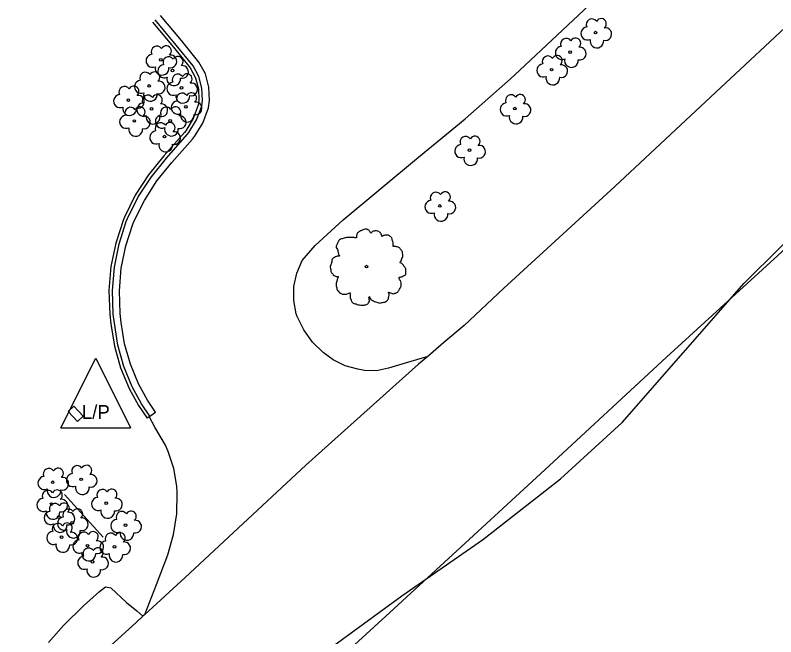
# Model space of a CAD drawing. Extents: x 2161152 to 2175754, y 602179 to 617749.
# Drawn here: x 2162727.5 to 2162836.6, y 605296.7 to 605385.9 of the extents above; entities that cross this region are included whole.
import ezdxf

# ---------------------------------------------------------------- set-up
doc = ezdxf.new("R2010")
doc.units = 0
for name, color, linetype in [('RD_EX_BldgApp_Sign', 7, 'Continuous'), ('RD_EX_Conc_Curb', 7, 'Continuous'), ('RD_EX_Conc_Gutter', 7, 'Continuous'), ('RD_EX_Parking_Asphalt', 7, 'Continuous'), ('RD_EX_Road', 7, 'Continuous'), ('RD_EX_UT', 7, 'Continuous'), ('RD_EX_VEG', 7, 'Continuous')]:
    doc.layers.add(name, color=color, linetype=linetype)

msp = doc.modelspace()

# ---------------------------------------------------------------- linework, layer by layer
at = {"layer": 'RD_EX_BldgApp_Sign'}
msp.add_line((2162734.54, 605317.11), (2162740.12, 605310.98), dxfattribs=at)
at = {"layer": 'RD_EX_Conc_Curb'}
msp.add_lwpolyline([(2162747.19, 605384.92), (2162750.21, 605381.32), (2162752.59, 605378.37), (2162753.36, 605376.93), (2162753.79, 605375.36), (2162753.85, 605373.72), (2162753.76, 605373), (2162753.04, 605371.1), (2162751.97, 605369.34), (2162751.78, 605369.09), (2162748.83, 605365.72), (2162746.62, 605363.02), (2162744.71, 605360.07), (2162743.16, 605356.93), (2162742.96, 605356.46), (2162741.9, 605353.2), (2162741.22, 605349.82), (2162740.94, 605346.39), (2162741.06, 605342.96), (2162741.22, 605341.61), (2162741.72, 605338.41), (2162742.61, 605335.29), (2162743.85, 605332.3), (2162745.2, 605329.87), (2162746.4, 605328.08), (2162746.4, 605328.09), (2162746.69, 605328.28), (2162746.81, 605328.36), (2162745.62, 605330.13), (2162744.29, 605332.55), (2162743.07, 605335.48), (2162742.21, 605338.54), (2162741.72, 605341.68), (2162741.56, 605343), (2162741.44, 605346.38), (2162741.72, 605349.75), (2162742.39, 605353.07), (2162743.43, 605356.29), (2162743.61, 605356.72), (2162745.15, 605359.82), (2162747.02, 605362.72), (2162749.21, 605365.4), (2162752.17, 605368.78), (2162752.38, 605369.06), (2162753.49, 605370.88), (2162754.25, 605372.88), (2162754.35, 605373.7), (2162754.29, 605375.44), (2162753.83, 605377.12), (2162753.01, 605378.65), (2162750.6, 605381.63), (2162747.57, 605385.24)], dxfattribs=at)
at = {"layer": 'RD_EX_Conc_Gutter'}
msp.add_lwpolyline([(2162746.81, 605328.36), (2162747.64, 605328.92), (2162746.48, 605330.66), (2162745.19, 605332.99), (2162744.02, 605335.81), (2162743.19, 605338.75), (2162742.71, 605341.82), (2162742.56, 605343.08), (2162742.45, 605346.36), (2162742.71, 605349.61), (2162743.35, 605352.82), (2162744.37, 605355.94), (2162744.52, 605356.31), (2162746.02, 605359.33), (2162747.83, 605362.13), (2162749.98, 605364.75), (2162752.94, 605368.14), (2162753.21, 605368.5), (2162754.39, 605370.44), (2162755.23, 605372.63), (2162755.36, 605373.65), (2162755.28, 605375.59), (2162754.77, 605377.49), (2162753.85, 605379.2), (2162751.37, 605382.27), (2162748.34, 605385.89)], dxfattribs=at)
at = {"layer": 'RD_EX_Parking_Asphalt'}
for points in [[(2162786.7, 605336.94), (2162783.47, 605335.98), (2162781.08, 605335.25), (2162779.36, 605334.88), (2162777.61, 605334.9), (2162776.68, 605335.08), (2162774.85, 605335.58), (2162773.13, 605336.43), (2162771.7, 605337.51), (2162770.15, 605338.99), (2162768.89, 605340.73), (2162767.97, 605342.67), (2162767.83, 605343.04), (2162767.46, 605344.98), (2162767.47, 605346.96), (2162767.88, 605348.9), (2162768.66, 605350.71), (2162770.55, 605352.84), (2162774.54, 605356.55), (2162785.35, 605365.55), (2162792.07, 605371.03), (2162798.56, 605376.79), (2162799.91, 605378.05), (2162815.23, 605392.44)], [(2162746.09, 605299.88), (2162747.78, 605304.17), (2162749.38, 605308.43), (2162750.22, 605311.34), (2162750.68, 605314.33), (2162750.75, 605317.36), (2162750.69, 605318.32), (2162750.26, 605320.85), (2162749.45, 605323.28), (2162749.04, 605324.19), (2162747.5, 605326.77), (2162746.69, 605328.28)]]:
    msp.add_lwpolyline(points, dxfattribs=at)
at = {"layer": 'RD_EX_Road'}
for points in [[(2162917.02, 605457), (2162901.98, 605443.14), (2162896.04, 605437.72), (2162894.14, 605435.98), (2162878, 605421.14), (2162857.37, 605402.08), (2162850.22, 605395.49), (2162842.2, 605388.11), (2162825.87, 605372.86), (2162813.54, 605361.31), (2162797.56, 605346.66), (2162791.94, 605341.38), (2162789, 605338.93), (2162786.7, 605336.94), (2162785.38, 605335.8), (2162769.2, 605321.32), (2162751.87, 605305.17), (2162746.09, 605299.88), (2162745.82, 605299.64), (2162744.83, 605298.73), (2162729.3, 605284.63)], [(2162610.98, 605142.74), (2162631.96, 605161.97), (2162654.13, 605182.45), (2162675.54, 605202.17), (2162697.6, 605222.63), (2162722.31, 605245.68), (2162738.68, 605260.91), (2162760.98, 605281.6), (2162781.23, 605300.15), (2162803.5, 605320.65), (2162820.96, 605336.83), (2162841.34, 605355.43), (2162863.86, 605376.35), (2162885.23, 605396.1), (2162904.45, 605413.96), (2162926, 605434.03)], [(2162732.26, 605295.86), (2162734.43, 605298.29), (2162737.28, 605301.11), (2162739.56, 605303.19), (2162740.43, 605303.86), (2162741.23, 605303.68), (2162743.47, 605301.6), (2162744.95, 605300.4), (2162745.82, 605299.64)]]:
    msp.add_lwpolyline(points, dxfattribs=at)
at = {"layer": 'RD_EX_UT'}
for p, q in [((2162734.04, 605326.67), (2162739.04, 605336.67)), ((2162739.04, 605336.67), (2162744.04, 605326.67)), ((2162734.04, 605326.67), (2162744.04, 605326.67))]:
    msp.add_line(p, q, dxfattribs=at)
msp.add_lwpolyline([(2162735.07, 605329.03), (2162736.42, 605327.59), (2162737.25, 605328.36), (2162735.9, 605329.81), (2162735.07, 605329.03)], dxfattribs=at)
at = {"layer": 'RD_EX_VEG'}
msp.add_lwpolyline([(2162768.94, 605292.32), (2162782.97, 605302.54), (2162794.55, 605310.58), (2162805.73, 605319.37), (2162814.62, 605327.42), (2162832.11, 605347.44), (2162847.75, 605362.93), (2162864.42, 605376.7), (2162880.18, 605392.38), (2162895.34, 605405.76), (2162910.37, 605417.3)], dxfattribs=at)
for centre, radius in [((2162810.79, 605383.42), 0.188), ((2162807.12, 605380.62), 0.188), ((2162748.37, 605379.5), 0.188), ((2162804.47, 605378.1), 0.188), ((2162750.05, 605377.98), 0.188), ((2162746.71, 605375.76), 0.188), ((2162751.36, 605375.48), 0.188), ((2162743.72, 605373.71), 0.188), ((2162751.99, 605372.76), 0.188), ((2162747.06, 605372.48), 0.188), ((2162799.2, 605372.51), 0.188), ((2162744.58, 605370.73), 0.188), ((2162749.71, 605370.76), 0.188), ((2162748.91, 605368.49), 0.188), ((2162792.68, 605366.53), 0.188), ((2162788.41, 605358.53), 0.188), ((2162777.91, 605349.82), 0.188), ((2162777.9, 605349.81), 0.000075), ((2162736.94, 605319.28), 0.188), ((2162732.86, 605318.86), 0.188), ((2162740.55, 605315.87), 0.188), ((2162732.71, 605315.73), 0.188), ((2162733.74, 605313.85), 0.188), ((2162735.66, 605313.03), 0.188), ((2162743.32, 605312.7), 0.188), ((2162734.14, 605310.99), 0.188), ((2162737.87, 605309.75), 0.188), ((2162741.74, 605309.59), 0.188), ((2162738.57, 605307.43), 0.188)]:
    msp.add_circle(centre, radius, dxfattribs=at)
for centre, radius, start, end in [((2162810.25, 605384.58), 0.813, 34.9763, 204.756), ((2162811.57, 605384.69), 0.746, 308.7626, 152.0467), ((2162809.62, 605383.3), 0.943, 96.4518, 294.734), ((2162812.17, 605383.21), 0.914, 256.5667, 98.1046), ((2162806.58, 605381.78), 0.813, 34.9763, 204.756), ((2162807.91, 605381.9), 0.746, 308.7626, 152.0467), ((2162810.97, 605382.22), 0.988, 166.8827, 5.7589), ((2162747.83, 605380.66), 0.813, 34.9763, 204.756), ((2162749.16, 605380.77), 0.746, 308.7626, 152.0467), ((2162805.95, 605380.5), 0.943, 96.4518, 294.734), ((2162808.5, 605380.41), 0.914, 256.5667, 98.1046), ((2162747.2, 605379.38), 0.943, 96.4518, 294.734), ((2162749.51, 605379.14), 0.813, 34.9763, 204.756), ((2162749.75, 605379.29), 0.914, 256.5667, 98.1046), ((2162750.84, 605379.26), 0.746, 308.7626, 152.0467), ((2162803.93, 605379.26), 0.813, 34.9763, 204.756), ((2162805.25, 605379.38), 0.746, 308.7626, 152.0467), ((2162807.31, 605379.42), 0.988, 166.8827, 5.7589), ((2162748.56, 605378.3), 0.988, 166.8827, 5.7589), ((2162748.88, 605377.87), 0.943, 96.4518, 294.734), ((2162751.43, 605377.77), 0.914, 256.5667, 98.1046), ((2162803.29, 605377.99), 0.943, 96.4518, 294.734), ((2162805.85, 605377.89), 0.914, 256.5667, 98.1046), ((2162746.17, 605376.92), 0.813, 34.9763, 204.756), ((2162747.49, 605377.03), 0.746, 308.7626, 152.0467), ((2162750.82, 605376.64), 0.813, 34.9763, 204.756), ((2162752.14, 605376.75), 0.746, 308.7626, 152.0467), ((2162745.54, 605375.64), 0.943, 96.4518, 294.734), ((2162748.09, 605375.55), 0.914, 256.5667, 98.1046), ((2162750.18, 605375.36), 0.943, 96.4518, 294.734), ((2162750.24, 605376.79), 0.988, 166.8827, 5.7589), ((2162752.74, 605375.27), 0.914, 256.5667, 98.1046), ((2162804.65, 605376.91), 0.988, 166.8827, 5.7589), ((2162743.18, 605374.87), 0.813, 34.9763, 204.756), ((2162744.5, 605374.99), 0.746, 308.7626, 152.0467), ((2162742.54, 605373.59), 0.943, 96.4518, 294.734), ((2162745.1, 605373.5), 0.914, 256.5667, 98.1046), ((2162746.52, 605373.64), 0.813, 34.9763, 204.756), ((2162746.89, 605374.56), 0.988, 166.8827, 5.7589), ((2162747.85, 605373.76), 0.746, 308.7626, 152.0467), ((2162751.54, 605374.28), 0.988, 166.8827, 5.7589), ((2162751.45, 605373.92), 0.813, 34.9763, 204.756), ((2162752.77, 605374.04), 0.746, 308.7626, 152.0467), ((2162798.66, 605373.67), 0.813, 34.9763, 204.756), ((2162799.98, 605373.79), 0.746, 308.7626, 152.0467), ((2162745.89, 605372.36), 0.943, 96.4518, 294.734), ((2162748.44, 605372.27), 0.914, 256.5667, 98.1046), ((2162750.82, 605372.65), 0.943, 96.4518, 294.734), ((2162753.37, 605372.55), 0.914, 256.5667, 98.1046), ((2162798.03, 605372.39), 0.943, 96.4518, 294.734), ((2162800.58, 605372.3), 0.914, 256.5667, 98.1046), ((2162743.9, 605372.51), 0.988, 166.8827, 5.7589), ((2162744.04, 605371.89), 0.813, 34.9763, 204.756), ((2162745.37, 605372.01), 0.746, 308.7626, 152.0467), ((2162749.17, 605371.92), 0.813, 34.9763, 204.756), ((2162750.5, 605372.03), 0.746, 308.7626, 152.0467), ((2162752.17, 605371.57), 0.988, 166.8827, 5.7589), ((2162743.41, 605370.62), 0.943, 96.4518, 294.734), ((2162745.96, 605370.52), 0.914, 256.5667, 98.1046), ((2162747.25, 605371.28), 0.988, 166.8827, 5.7589), ((2162748.54, 605370.64), 0.943, 96.4518, 294.734), ((2162751.09, 605370.55), 0.914, 256.5667, 98.1046), ((2162799.38, 605371.31), 0.988, 166.8827, 5.7589), ((2162744.77, 605369.53), 0.988, 166.8827, 5.7589), ((2162748.37, 605369.65), 0.813, 34.9763, 204.756), ((2162749.9, 605369.56), 0.988, 166.8827, 5.7589), ((2162749.69, 605369.77), 0.746, 308.7626, 152.0467), ((2162747.73, 605368.37), 0.943, 96.4518, 294.734), ((2162750.29, 605368.28), 0.914, 256.5667, 98.1046), ((2162792.14, 605367.69), 0.813, 34.9763, 204.756), ((2162793.47, 605367.8), 0.746, 308.7626, 152.0467), ((2162749.09, 605367.29), 0.988, 166.8827, 5.7589), ((2162791.51, 605366.41), 0.943, 96.4518, 294.734), ((2162794.06, 605366.32), 0.914, 256.5667, 98.1046), ((2162792.87, 605365.33), 0.988, 166.8827, 5.7589), ((2162787.87, 605359.69), 0.813, 34.9763, 204.756), ((2162789.2, 605359.81), 0.746, 308.7626, 152.0467), ((2162787.24, 605358.41), 0.943, 96.4518, 294.734), ((2162789.79, 605358.32), 0.914, 256.5667, 98.1046), ((2162788.6, 605357.33), 0.988, 166.8827, 5.7589), ((2162732.32, 605320.02), 0.813, 34.9763, 204.756), ((2162733.65, 605320.14), 0.746, 308.7626, 152.0467), ((2162736.4, 605320.44), 0.813, 34.9763, 204.756), ((2162737.72, 605320.56), 0.746, 308.7626, 152.0467), ((2162731.69, 605318.75), 0.943, 96.4518, 294.734), ((2162734.24, 605318.65), 0.914, 256.5667, 98.1046), ((2162735.77, 605319.17), 0.943, 96.4518, 294.734), ((2162738.32, 605319.07), 0.914, 256.5667, 98.1046), ((2162737.12, 605318.09), 0.988, 166.8827, 5.7589), ((2162732.17, 605316.89), 0.813, 34.9763, 204.756), ((2162733.05, 605317.67), 0.988, 166.8827, 5.7589), ((2162733.49, 605317.01), 0.746, 308.7626, 152.0467), ((2162740.01, 605317.03), 0.813, 34.9763, 204.756), ((2162741.34, 605317.14), 0.746, 308.7626, 152.0467), ((2162731.54, 605315.61), 0.943, 96.4518, 294.734), ((2162734.09, 605315.52), 0.914, 256.5667, 98.1046), ((2162739.38, 605315.75), 0.943, 96.4518, 294.734), ((2162741.93, 605315.66), 0.914, 256.5667, 98.1046), ((2162733.2, 605315.01), 0.813, 34.9763, 204.756), ((2162734.53, 605315.13), 0.746, 308.7626, 152.0467), ((2162735.12, 605314.2), 0.813, 34.9763, 204.756), ((2162736.44, 605314.31), 0.746, 308.7626, 152.0467), ((2162732.57, 605313.73), 0.943, 96.4518, 294.734), ((2162732.89, 605314.53), 0.988, 166.8827, 5.7589), ((2162735.12, 605313.64), 0.914, 256.5667, 98.1046), ((2162740.74, 605314.67), 0.988, 166.8827, 5.7589), ((2162742.78, 605313.86), 0.813, 34.9763, 204.756), ((2162744.11, 605313.98), 0.746, 308.7626, 152.0467), ((2162733.6, 605312.15), 0.813, 34.9763, 204.756), ((2162733.93, 605312.65), 0.988, 166.8827, 5.7589), ((2162734.49, 605312.92), 0.943, 96.4518, 294.734), ((2162734.92, 605312.27), 0.746, 308.7626, 152.0467), ((2162737.04, 605312.83), 0.914, 256.5667, 98.1046), ((2162742.15, 605312.59), 0.943, 96.4518, 294.734), ((2162744.7, 605312.49), 0.914, 256.5667, 98.1046), ((2162732.96, 605310.87), 0.943, 96.4518, 294.734), ((2162735.84, 605311.84), 0.988, 166.8827, 5.7589), ((2162735.52, 605310.78), 0.914, 256.5667, 98.1046), ((2162737.33, 605310.91), 0.813, 34.9763, 204.756), ((2162738.65, 605311.03), 0.746, 308.7626, 152.0467), ((2162743.51, 605311.51), 0.988, 166.8827, 5.7589), ((2162741.2, 605310.75), 0.813, 34.9763, 204.756), ((2162742.53, 605310.87), 0.746, 308.7626, 152.0467), ((2162734.32, 605309.79), 0.988, 166.8827, 5.7589), ((2162736.69, 605309.63), 0.943, 96.4518, 294.734), ((2162739.25, 605309.54), 0.914, 256.5667, 98.1046), ((2162740.57, 605309.47), 0.943, 96.4518, 294.734), ((2162743.12, 605309.38), 0.914, 256.5667, 98.1046), ((2162738.05, 605308.55), 0.988, 166.8827, 5.7589), ((2162738.03, 605308.59), 0.813, 34.9763, 204.756), ((2162739.35, 605308.7), 0.746, 308.7626, 152.0467), ((2162741.93, 605308.39), 0.988, 166.8827, 5.7589), ((2162737.39, 605307.31), 0.943, 96.4518, 294.734), ((2162739.95, 605307.22), 0.914, 256.5667, 98.1046), ((2162738.75, 605306.23), 0.988, 166.8827, 5.7589)]:
    msp.add_arc(centre, radius, start, end, dxfattribs=at)
for points in [[(2162778.01, 605355.2), (2162777.78, 605355.22), (2162777.54, 605355.14), (2162777.35, 605355.07), (2162777.18, 605355.01), (2162777.01, 605354.94), (2162776.79, 605354.8), (2162776.62, 605354.65), (2162776.53, 605354.47), (2162776.49, 605354.3), (2162776.45, 605354.09), (2162776.45, 605353.96), (2162776.36, 605353.94), (2162776.24, 605353.96), (2162776.06, 605354.02), (2162775.87, 605354.02), (2162775.68, 605354.02), (2162775.42, 605354), (2162775.16, 605354), (2162774.95, 605353.96), (2162774.71, 605353.92), (2162774.43, 605353.83), (2162774.16, 605353.74), (2162773.94, 605353.55), (2162773.75, 605353.19), (2162773.66, 605352.93), (2162773.55, 605352.74), (2162773.66, 605352.41), (2162773.79, 605352.14), (2162773.81, 605351.99), (2162773.86, 605351.67), (2162773.94, 605351.51), (2162774.03, 605351.36), (2162773.98, 605351.34), (2162773.7, 605351.3), (2162773.47, 605351.22), (2162773.15, 605351.06), (2162772.98, 605350.89), (2162772.91, 605350.64), (2162772.89, 605350.38), (2162772.82, 605350.23), (2162772.76, 605350.03), (2162772.74, 605349.97), (2162772.7, 605349.73), (2162772.78, 605349.39), (2162772.8, 605349.13), (2162772.89, 605348.96), (2162773, 605348.83), (2162773.13, 605348.64), (2162773.43, 605348.47), (2162773.68, 605348.39), (2162773.83, 605348.38), (2162773.7, 605348), (2162773.66, 605347.74), (2162773.56, 605347.44), (2162773.56, 605347.38), (2162773.53, 605347.03), (2162773.64, 605346.78), (2162773.7, 605346.5), (2162773.83, 605346.33), (2162774.03, 605346.11), (2162774.28, 605345.94), (2162774.65, 605345.85), (2162774.95, 605345.86), (2162775.38, 605346), (2162775.57, 605346.05), (2162775.55, 605345.92), (2162775.57, 605345.64), (2162775.57, 605345.32), (2162775.68, 605345.08), (2162775.76, 605344.87), (2162775.87, 605344.68), (2162776.11, 605344.52), (2162776.41, 605344.46), (2162776.73, 605344.35), (2162777.07, 605344.29), (2162777.44, 605344.27), (2162777.89, 605344.38), (2162778.1, 605344.48), (2162778.18, 605344.61), (2162778.33, 605344.89), (2162778.29, 605345.06), (2162778.31, 605345.51), (2162778.38, 605345.38), (2162778.51, 605345.11), (2162778.89, 605344.89), (2162779.19, 605344.76), (2162779.54, 605344.65), (2162779.77, 605344.59), (2162780.12, 605344.65), (2162780.41, 605344.7), (2162780.69, 605344.8), (2162780.91, 605345), (2162781.04, 605345.21), (2162781.08, 605345.41), (2162781.14, 605345.7), (2162781.17, 605345.83)], [(2162781.17, 605345.83), (2162781.12, 605345.96), (2162781.08, 605346.15), (2162781.14, 605346.13), (2162781.27, 605346.09), (2162781.47, 605346), (2162781.64, 605345.94), (2162781.89, 605345.96), (2162782.09, 605346.03), (2162782.43, 605346.24), (2162782.64, 605346.6), (2162782.84, 605346.9), (2162782.9, 605347.14), (2162782.86, 605347.31), (2162782.84, 605347.68), (2162782.69, 605347.87), (2162782.65, 605347.96), (2162782.58, 605348.26), (2162782.64, 605348.3), (2162782.84, 605348.34), (2162783.12, 605348.43), (2162783.33, 605348.53), (2162783.5, 605348.66), (2162783.55, 605348.83), (2162783.54, 605349.13), (2162783.57, 605349.43), (2162783.52, 605349.54), (2162783.44, 605349.65), (2162783.39, 605349.8), (2162783.27, 605349.91), (2162783.2, 605350.03), (2162783.12, 605350.1), (2162783.03, 605350.21), (2162782.9, 605350.31), (2162782.79, 605350.34), (2162782.75, 605350.46), (2162782.86, 605350.61), (2162782.9, 605350.68), (2162782.92, 605350.85), (2162783.09, 605351.11), (2162783.12, 605351.41), (2162783.09, 605351.73), (2162783.05, 605351.94), (2162782.94, 605352.14), (2162782.79, 605352.33), (2162782.69, 605352.46), (2162782.56, 605352.56), (2162782.32, 605352.65), (2162782.13, 605352.69), (2162781.87, 605352.69), (2162781.72, 605352.72), (2162781.74, 605352.76), (2162781.74, 605352.87), (2162781.74, 605353.08), (2162781.68, 605353.42), (2162781.57, 605353.79), (2162781.57, 605353.81), (2162781.49, 605354), (2162781.32, 605354.15), (2162781.19, 605354.22), (2162781.04, 605354.32), (2162780.86, 605354.34), (2162780.63, 605354.34), (2162780.42, 605354.3), (2162780.27, 605354.22), (2162780.14, 605354.13), (2162780.09, 605354.24), (2162780.01, 605354.47), (2162779.97, 605354.58), (2162779.86, 605354.71), (2162779.69, 605354.86), (2162779.36, 605354.95), (2162778.89, 605354.9), (2162778.66, 605354.75), (2162778.55, 605354.62), (2162778.51, 605354.71), (2162778.36, 605354.86), (2162778.29, 605354.99), (2162778.16, 605355.09), (2162778.04, 605355.16), (2162777.97, 605355.2)]]:
    msp.add_spline(points, degree=3, dxfattribs=at)

# ---------------------------------------------------------------- texts
at = {"layer": 'RD_EX_UT'}
msp.add_text('L/P', height=2, dxfattribs=at).set_placement((2162737.04, 605327.95))

doc.saveas('drawing.dxf')
